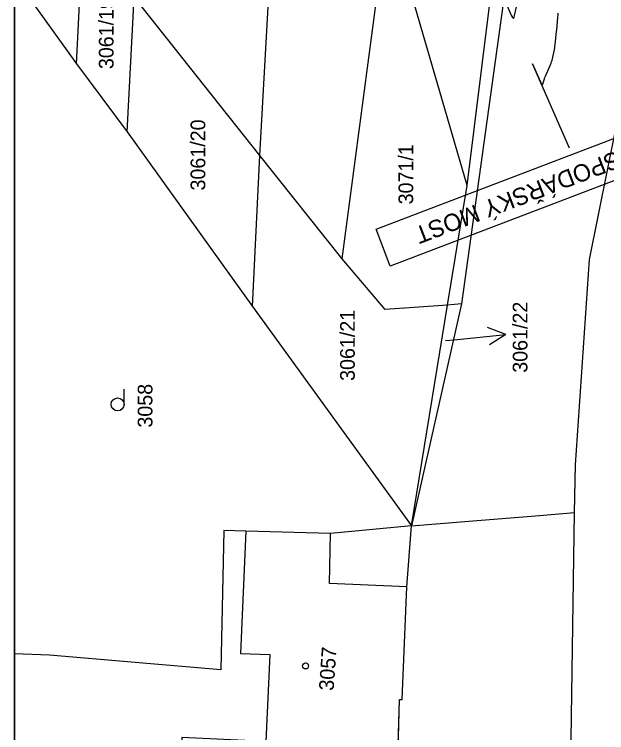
# Model space of a CAD drawing. Extents: x -534410 to -534262, y -1190162 to -1189584.
# Drawn here: x -534410.13 to -534375.88, y -1189988.43 to -1189946.91 of the extents above; entities that cross this region are included whole.
import ezdxf

# ---------------------------------------------------------------- set-up
doc = ezdxf.new("R2010")
doc.units = 0
for name, color, linetype in [('30', 7, 'Continuous'), ('31', 7, 'Continuous'), ('_N_text', 7, 'Continuous'), ('_rámeček', 7, 'Continuous'), ('_rámeček_mřížka', 7, 'Continuous'), ('Hranice parcel', 7, 'Continuous'), ('Parcelní čísla', 7, 'Continuous'), ('Polygon budovy', 7, 'Continuous'), ('Pop  PČ popisy', 7, 'Continuous'), ('Značky budov', 7, 'Continuous'), ('Značky kultur', 7, 'Continuous')]:
    doc.layers.add(name, color=color, linetype=linetype)

msp = doc.modelspace()

# ---------------------------------------------------------------- linework, layer by layer
at = {"layer": '30'}
msp.add_lwpolyline([(-534383.296, -1189942.636), (-534381.381, -1189946.992), (-534381.325, -1189947.092), (-534381.276, -1189947.123), (-534381.234, -1189947.083), (-534381.198, -1189946.974), (-534381.07, -1189946.397)], dxfattribs=at)
at = {"layer": '31'}
msp.add_lwpolyline([(-534378.02, -1189954.638), (-534380.16, -1189949.769), (-534380.099, -1189949.909), (-534379.628, -1189950.98), (-534379.618, -1189950.997), (-534379.609, -1189951.002), (-534379.6, -1189950.996), (-534379.592, -1189950.979), (-534379.557, -1189950.889), (-534379.549, -1189950.867), (-534379.541, -1189950.844), (-534379.533, -1189950.821), (-534379.526, -1189950.799), (-534379.474, -1189950.626), (-534379.463, -1189950.59), (-534379.45, -1189950.554), (-534379.436, -1189950.519), (-534379.422, -1189950.484), (-534379.095, -1189949.734), (-534379.061, -1189949.649), (-534379.031, -1189949.563), (-534379.006, -1189949.475), (-534378.985, -1189949.385), (-534378.91, -1189949.025), (-534378.893, -1189948.934), (-534378.878, -1189948.844), (-534378.865, -1189948.753), (-534378.854, -1189948.661), (-534378.772, -1189947.884), (-534378.771, -1189947.872), (-534378.769, -1189947.86), (-534378.765, -1189947.837), (-534378.763, -1189947.825), (-534378.761, -1189947.813), (-534378.695, -1189947.074), (-534378.686, -1189946.959), (-534378.679, -1189946.844)], dxfattribs=at)
at = {"layer": '_N_text'}
msp.add_lwpolyline([(-534358.995, -1189950.253), (-534388.393, -1189961.469), (-534389.213, -1189959.319), (-534359.815, -1189948.103)], close=True, dxfattribs=at)
at = {"layer": '_rámeček'}
msp.add_line((-534410.126, -1189584.47), (-534410.126, -1190161.97), dxfattribs=at)
msp.add_lwpolyline([(-534410.126, -1189899.47), (-534261.626, -1189899.47), (-534261.626, -1190004.47), (-534410.126, -1190004.47)], close=True, dxfattribs=at)
at = {"layer": '_rámeček_mřížka'}
msp.add_line((-534410.126, -1189584.47), (-534410.126, -1190161.97), dxfattribs=at)
at = {"layer": 'Hranice parcel'}
for p, q in [((-534391.18, -1189961.04), (-534385.61, -1189919.11)), ((-534406.54, -1189949.77), (-534406.13, -1189942)), ((-534410.126, -1189944.756), (-534406.54, -1189949.77)), ((-534403.61, -1189953.7), (-534403.19, -1189945.91)), ((-534395.93, -1189955.06), (-534403.19, -1189945.91)), ((-534406.54, -1189949.77), (-534403.61, -1189953.7)), ((-534403.61, -1189953.7), (-534396.36, -1189963.8)), ((-534396.36, -1189963.8), (-534395.93, -1189955.06)), ((-534391.18, -1189961.04), (-534395.93, -1189955.06)), ((-534385.09, -1189963.71), (-534383.94, -1189956.8)), ((-534396.36, -1189963.8), (-534387.17, -1189976.47)), ((-534384.28, -1189963.65), (-534387.17, -1189976.47)), ((-534387.17, -1189976.47), (-534385.09, -1189963.71)), ((-534384.28, -1189963.65), (-534385.09, -1189963.71)), ((-534388.01, -1189991.75), (-534387.85, -1189986.52))]:
    msp.add_line(p, q, dxfattribs=at)
for points in [[(-534395.93, -1189955.06), (-534393.76, -1189916.2), (-534389.49, -1189774.63), (-534390.92, -1189749.37)], [(-534383.94, -1189956.8), (-534379.19, -1189918.48), (-534376.74, -1189853.94), (-534375.92, -1189797.44), (-534376.41, -1189774.02), (-534378.12, -1189750.26)], [(-534373.61, -1189764.09), (-534375.04, -1189897.07), (-534384.28, -1189963.65)], [(-534383.94, -1189956.8), (-534387.37, -1189945.01), (-534385.61, -1189919.11)], [(-534377.74, -1189975.71), (-534377.67, -1189972.94), (-534376.87, -1189961.07), (-534375.31, -1189953.34)], [(-534385.09, -1189963.71), (-534388.68, -1189963.97), (-534391.18, -1189961.04)], [(-534387.17, -1189976.47), (-534383.85, -1189976.2), (-534379.76, -1189975.87), (-534377.74, -1189975.71)], [(-534380.79, -1190075.34), (-534378.76, -1190045.09), (-534377.74, -1189975.71)], [(-534387.17, -1189976.47), (-534391.84, -1189976.92), (-534396.75, -1189976.78), (-534398.02, -1189976.74), (-534398.19, -1189984.8), (-534408.09, -1189983.96), (-534410.126, -1189983.877)], [(-534387.85, -1189986.52), (-534387.71, -1189986.52), (-534387.44, -1189980.01), (-534387.17, -1189976.47)]]:
    msp.add_lwpolyline(points, dxfattribs=at)
at = {"layer": 'Polygon budovy'}
msp.add_lwpolyline([(-534397.05, -1189983.85), (-534395.35, -1189983.92), (-534395.59, -1189988.94), (-534400.44, -1189988.72), (-534400.58, -1189991.34), (-534398.09, -1189991.44), (-534388.01, -1189991.75), (-534387.85, -1189986.52), (-534387.71, -1189986.52), (-534387.44, -1189980.01), (-534391.9, -1189979.81), (-534391.84, -1189976.92), (-534396.75, -1189976.78)], close=True, dxfattribs=at)
at = {"layer": 'Pop  PČ popisy'}
for p, q in [((-534381.715, -1189965.406), (-534382.764, -1189965.013)), ((-534384.7, -1189965.72), (-534381.715, -1189965.406)), ((-534381.715, -1189965.406), (-534382.659, -1189966.009)), ((-534385.2, -1189965.77), (-534384.7, -1189965.72))]:
    msp.add_line(p, q, dxfattribs=at)
at = {"layer": 'Značky budov'}
msp.add_circle((-534393.29, -1189984.577), 0.175, dxfattribs=at)
at = {"layer": 'Značky kultur'}
msp.add_line((-534403.782, -1189969.455), (-534403.782, -1189968.58), dxfattribs=at)
msp.add_circle((-534404.157, -1189969.455), 0.375, dxfattribs=at)

# ---------------------------------------------------------------- texts
at = {"layer": '_N_text'}
msp.add_text('Ř. KM 0,6272 - 0,6377: HOSPODÁŘSKÝ MOST', height=1, rotation=200.9032, dxfattribs=at).set_placement((-534360.199, -1189948.996))
at = {"layer": 'Parcelní čísla'}
for s, rotation, p in [('3061/19', 90, (-534404.39, -1189950.071)), ('3061/20', 90, (-534399.086, -1189957.089)), ('3071/1', 90, (-534387.065, -1189957.891)), ('3061/22', 90, (-534380.458, -1189967.626)), ('3061/21', 90, (-534390.442, -1189968.097)), ('3058', 90, (-534402.143, -1189970.798)), ('3057', 86, (-534391.669, -1189986.029))]:
    msp.add_text(s, height=0.85, rotation=rotation, dxfattribs=at).set_placement(p)

doc.saveas('drawing.dxf')
